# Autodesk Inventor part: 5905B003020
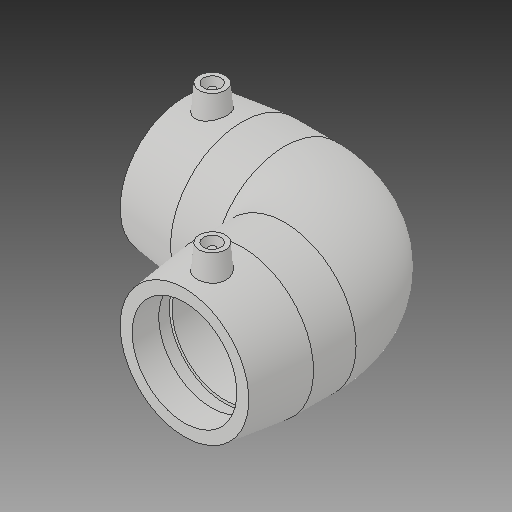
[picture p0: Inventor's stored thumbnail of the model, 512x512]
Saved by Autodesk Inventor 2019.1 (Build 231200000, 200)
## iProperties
Created: 2017-06
Part Number: 5905B003020
Material: Generic
Description: PLASSON 90° ELBOW ASTM 2''
Document SubType Name: Modeling
Designer: KIM
Mass: 55.0731 g
Surface Area: 148.067 cm^2
Volume: 55.0731 cm^3
Density: 1 g/cm^3
Appearance: Default
Author: KIM
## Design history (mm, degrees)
derived "5905B.ipt"
feature "Solid1::5905B.ipt"
tag "TaggingFeature1"
body "Solid1"
other parameters: "d_" = 60.1, "L_" = 132.08, "L_1" = 57.404, "D_" = 82.042, "A_" = 51.816, "d2" = 82.042, "d4" = 33.02, "d5" = 73.8378, "d8" = 168 deg, "d10" = 22.9616, "d11" = 7.65387, "d14" = 17.6296, "d18" = 60.1, "d19" = 3.52592, "d20" = 168 deg, "d22" = 75.47864, "d23" = 82.042, "d24" = 73.21428, "d29" = 51.816, "d30" = 15, "d31" = 79.248, "d34" = 5 deg, "d35" = 15, "d39" = 5 deg, "d41" = 4, "d42" = 14, "d43" = 0, "d45" = 4, "d46" = 14, "d47" = 0, "d49" = 60.1, "d50" = 51.085, "d51" = 22.9616, "d52" = 57.404, "d54" = 90 deg, "d65" = 60.1, "d67" = 45 deg, "d71" = 90 deg, "d75" = 4.1021, "d82" = 45 deg, "d83" = 57.404, "d84" = 73.8378, "d86" = 36.9189, "d87" = 90 deg, "d90" = 57.404, "d91" = 0, "d92" = 57.404, "d93" = 0, "d94" = 90 deg, "d95" = 37.73932, "d98" = 132.08, "d101" = 3, "d102" = 0, "d103" = 3, "d104" = 0, "d105" = 16.64716, "d106" = 4.16179, "d107" = 132.08, "d110" = 31.5722
